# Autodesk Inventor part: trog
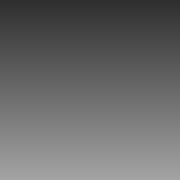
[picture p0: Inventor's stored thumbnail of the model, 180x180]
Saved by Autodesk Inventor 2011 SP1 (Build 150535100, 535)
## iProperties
Created: 2010-04
Part Number: trog
Document SubType Name: Modeling
Designer: V.de Jong
Density: 1 g/cm^3
Author: V.de Jong
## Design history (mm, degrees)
node "Blocks"
  sketch "Trog"
    geometry: L1 (0, 0)-(0, -300); L2 (144.181, 0)-(75.071, -275.091); L3 (50.825, -294)-(-50.825, -294); L4 (-75.071, -275.091)-(-144.181, 0); L5 (144.181, 0)-(150, -1.462); L6 (-144.181, 0)-(-150, -1.462); L7 (-144.181, 0)-(144.181, 0); L8 (150, -1.462)-(80.89, -276.553); L9 (50.825, -300)-(-50.825, -300); L10 (-80.89, -276.553)-(-150, -1.462); A1 r 31 centre (50.825, -269) between (50.825, -300) and (80.89, -276.553); A2 r 25 centre (50.825, -269) between (50.825, -294) and (75.071, -275.091); A3 r 25 centre (-50.825, -269) between (-75.071, -275.091) and (-50.825, -294); A4 r 31 centre (-50.825, -269) between (-80.89, -276.553) and (-50.825, -300); 3 further points
    constraints: 20 end point, 8 point on circle, 6 tangent, 4 centre point, 4 point on line, 3 perpendicular, 2 horizontal, 2 midpoint, 1 coincident, 1 equal radius, 1 parallel, 1 vertical alignment, 2 other
    dimensions: "Grootste_Been_Breedte" = 300 distance of L6.end L5.end; "Kleinste_Been_Breedte" = 150 distance of point (75, -300) point (-75, -300); "Min_Radius" = 25 radius of A3; "Plaat_dikte" = 6 distance between parallel lines of L4 L10; "Trog_Hoogte" = 300 distance between parallel lines of L9 L7
